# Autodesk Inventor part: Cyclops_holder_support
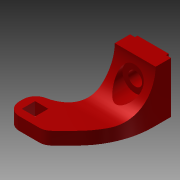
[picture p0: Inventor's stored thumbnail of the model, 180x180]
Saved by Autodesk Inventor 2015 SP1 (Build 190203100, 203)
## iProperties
Created: 2015-09
Part Number: Cyclops_holder_support
Material: Generic
Document SubType Name: Modeling
Designer: egor
Density: 1 g/cm^3
Appearance: Default
Author: egor
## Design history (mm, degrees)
sketch "Sketch1"
  geometry: L1 (-2.6, -2.6)-(2.6, -2.6); L2 (2.6, -2.6)-(2.6, 2.6); L3 (2.6, 2.6)-(-2.6, 2.6); L4 (-2.6, 2.6)-(-2.6, -2.6); L5 (-5.6, -5.6)-(9.35, -5.6); L6 (-3.65, 5.6)-(-5.6, 5.6); L7 (-5.6, 5.6)-(-5.6, -5.6); L8 (8.35, 28.85)-(24.35, 28.85); L9 (24.35, 28.85)-(24.35, 21.826); L10 (24.35, 22.85)-(8.35, 22.85); L11 (8.35, 17.6)-(8.35, 28.85); L12 (15.563, 0.613)-(9.35, -5.6); L13 (10.25, 28.85)-(22.45, 28.85); L14 (22.45, 28.85)-(22.45, 29.85); L15 (22.45, 29.85)-(10.25, 29.85); L16 (10.25, 29.85)-(10.25, 28.85); A1 r 12 centre (-3.65, 17.6) between (-3.65, 5.6) and (8.35, 17.6); A2 r 30 centre (-5.65, 21.826) between (15.563, 0.613) and (24.35, 21.826); 8 further points
  constraints: 32 end point, 7 parallel, 7 point on line, 6 midpoint, 4 horizontal, 4 point on circle, 4 tangent, 3 perpendicular, 2 centre point, 2 horizontal alignment, 2 vertical alignment
  dimensions: "d0" = 5.2 distance of L3.end L2.end; "d1" = 5.2 distance of L2.end L1.end; "d4" = 16 distance of L10.start L10.end; "d5" = 6 distance of L8.end L10.start; "d8" = 12 radius of A1; "d9" = 15 distance of point (24.35, 9.4) point (24.35, -5.6); "d10" = 15 distance of L5.end point (24.35, -5.6) (= d9); "d11" = 13.75 distance from line of point (16.35, 28.85) L2; "d12" = 3 distance between parallel lines of L7 L4; "d13" = 3 distance between parallel lines of L1 L5 (= d12); "d14" = 30 radius of A2; "d15" = 12.2 distance of L15.end L14.end; "d16" = 1 distance of L13.end L14.end; "d30" = 26.25 distance between parallel lines of L3 L8
extrude "Extrusion1" new body sketch "Sketch1" distance "d17" = 20; taper "d18" = 0 deg
extrude "Extrusion2" join sketch "Sketch1" distance "d19" = 5; taper "d20" = 0 deg
sketch "Sketch2"
  geometry: L1 (0, 20)-(16, 20) reference; C1 r 2.7 at (8, 12); C2 r 5 at (8, 12); 1 further point
  constraints: 2 centre point, 1 coincident
  dimensions: "d21" = 5.4 diameter of C1; "d22" = 10 diameter of C2; "d23" = 8 distance from line of C1.centre L1
fillet "Fillet1" dims "d24" = 15
extrude "Extrusion3" cut sketch "Sketch2" stored distance "d25" = 5; taper "d26" = 0 deg
extrude "Extrusion4" cut sketch "Sketch2" stored distance "d27" = 5.4 (= d21); taper "d28" = 0 deg
fillet "Fillet2" dims "d29" = 5
body "Solid1"
